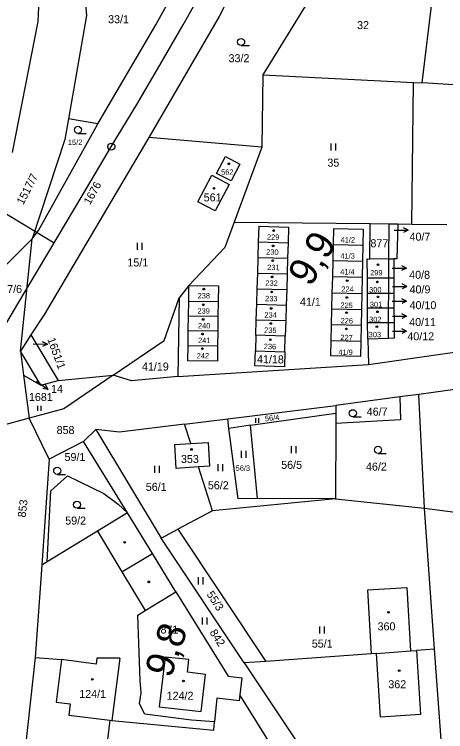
# Model space of a CAD drawing. Extents: x -553916 to -552953, y -1067469 to -1066637.
# Drawn here: x -553569.1 to -553477.6, y -1067307 to -1067154.7 of the extents above; entities that cross this region are included whole.
import ezdxf

# ---------------------------------------------------------------- set-up
doc = ezdxf.new("R2010")
doc.units = 0
for name, color, linetype in [('Hranice parcel', 7, 'Continuous'), ('Kolej', 7, 'Continuous'), ('Návěst místo trati', 7, 'Continuous'), ('Parcelní čísla', 7, 'Continuous'), ('Pop  PČ popisy', 7, 'Continuous'), ('Propustek', 7, 'Continuous'), ('Vnitřní kresba', 7, 'Continuous'), ('Vrstva 1', 7, 'Continuous'), ('Značky budov', 7, 'Continuous'), ('Značky kultur', 7, 'Continuous')]:
    doc.layers.add(name, color=color, linetype=linetype)

msp = doc.modelspace()

# ---------------------------------------------------------------- linework, layer by layer
at = {"layer": 'Hranice parcel'}
for p, q in [((-553499.73, -1067140.34), (-553516.39, -1067167.53)), ((-553499.73, -1067140.34), (-553516.39, -1067167.53)), ((-553482.63, -1067169.28), (-553479.18, -1067140.92)), ((-553516.39, -1067167.53), (-553516.62, -1067182.93)), ((-553516.39, -1067167.53), (-553516.62, -1067182.93)), ((-553516.39, -1067167.53), (-553484.43, -1067169.19)), ((-553484.83, -1067199.23), (-553484.43, -1067169.19)), ((-553484.43, -1067169.19), (-553482.63, -1067169.28)), ((-553551.38, -1067177.98), (-553557.64, -1067176.88)), ((-553516.62, -1067182.93), (-553540.6, -1067180.86)), ((-553516.62, -1067182.93), (-553522.52, -1067198.86)), ((-553516.62, -1067182.93), (-553522.52, -1067198.86)), ((-553522.52, -1067198.86), (-553493.67, -1067199.14)), ((-553493.69, -1067206.69), (-553493.67, -1067199.14)), ((-553493.67, -1067199.14), (-553489.7, -1067199.18)), ((-553489.7, -1067199.18), (-553489.74, -1067206.64)), ((-553489.7, -1067199.18), (-553487.77, -1067199.2)), ((-553487.77, -1067199.2), (-553484.83, -1067199.23)), ((-553484.83, -1067199.23), (-553477.39, -1067199.3)), ((-553517.41, -1067206.32), (-553517.31, -1067203.01)), ((-553517.31, -1067203.01), (-553511.06, -1067203.19)), ((-553511.06, -1067203.19), (-553511.16, -1067206.5)), ((-553501.52, -1067207), (-553501.44, -1067203.6)), ((-553501.44, -1067203.6), (-553495.2, -1067203.73)), ((-553495.2, -1067203.73), (-553495.27, -1067207.14)), ((-553517.5, -1067209.63), (-553517.41, -1067206.32)), ((-553517.41, -1067206.32), (-553511.16, -1067206.5)), ((-553511.16, -1067206.5), (-553511.26, -1067209.81)), ((-553501.59, -1067210.41), (-553501.52, -1067207)), ((-553501.52, -1067207), (-553495.27, -1067207.14)), ((-553495.27, -1067207.14), (-553495.34, -1067210.55)), ((-553489.74, -1067206.64), (-553493.69, -1067206.69)), ((-553489.74, -1067206.64), (-553489.76, -1067210.67)), ((-553489.74, -1067206.64), (-553488.62, -1067206.63)), ((-553488.62, -1067206.63), (-553488.61, -1067210.66)), ((-553517.6, -1067212.97), (-553517.5, -1067209.63)), ((-553517.5, -1067209.63), (-553511.26, -1067209.81)), ((-553511.26, -1067209.81), (-553511.35, -1067213.12)), ((-553501.67, -1067213.82), (-553501.59, -1067210.41)), ((-553495.34, -1067210.55), (-553501.59, -1067210.41)), ((-553495.34, -1067210.55), (-553495.42, -1067213.96)), ((-553494.21, -1067210.69), (-553489.76, -1067210.67)), ((-553494.2, -1067213.93), (-553494.21, -1067210.69)), ((-553489.76, -1067210.67), (-553489.78, -1067213.91)), ((-553489.76, -1067210.67), (-553488.61, -1067210.66)), ((-553488.61, -1067210.66), (-553488.6, -1067213.9)), ((-553532.09, -1067212.3), (-553534.18, -1067214.93)), ((-553532.09, -1067212.3), (-553534.18, -1067214.93)), ((-553517.7, -1067216.24), (-553517.6, -1067212.97)), ((-553517.6, -1067212.97), (-553511.35, -1067213.12)), ((-553511.35, -1067213.12), (-553511.45, -1067216.43)), ((-553534.18, -1067214.93), (-553534.41, -1067231.61)), ((-553501.74, -1067217.23), (-553501.67, -1067213.82)), ((-553501.67, -1067213.82), (-553495.42, -1067213.96)), ((-553495.42, -1067213.96), (-553495.49, -1067217.37)), ((-553494.2, -1067213.93), (-553489.78, -1067213.91)), ((-553494.18, -1067217.04), (-553494.2, -1067213.93)), ((-553489.78, -1067213.91), (-553489.8, -1067217.02)), ((-553489.78, -1067213.91), (-553488.6, -1067213.9)), ((-553488.6, -1067213.9), (-553488.59, -1067217.02)), ((-553532.18, -1067218.74), (-553532.14, -1067215.62)), ((-553532.14, -1067215.62), (-553525.89, -1067215.7)), ((-553525.89, -1067215.7), (-553525.93, -1067218.82)), ((-553517.8, -1067219.55), (-553517.7, -1067216.24)), ((-553517.7, -1067216.24), (-553511.45, -1067216.43)), ((-553511.45, -1067216.43), (-553511.55, -1067219.74)), ((-553501.82, -1067220.64), (-553501.74, -1067217.23)), ((-553501.74, -1067217.23), (-553495.49, -1067217.37)), ((-553495.49, -1067217.37), (-553495.57, -1067220.78)), ((-553494.18, -1067217.04), (-553489.8, -1067217.02)), ((-553494.17, -1067220.15), (-553494.18, -1067217.04)), ((-553489.8, -1067217.02), (-553489.82, -1067220.13)), ((-553489.8, -1067217.02), (-553488.59, -1067217.02)), ((-553488.59, -1067217.02), (-553488.57, -1067220.13)), ((-553532.22, -1067221.86), (-553532.18, -1067218.74)), ((-553532.18, -1067218.74), (-553525.93, -1067218.82)), ((-553525.93, -1067218.82), (-553525.97, -1067221.94)), ((-553517.89, -1067222.86), (-553517.8, -1067219.55)), ((-553517.8, -1067219.55), (-553511.55, -1067219.74)), ((-553511.55, -1067219.74), (-553511.65, -1067223.05)), ((-553501.89, -1067224.05), (-553501.82, -1067220.64)), ((-553495.57, -1067220.78), (-553501.82, -1067220.64)), ((-553495.57, -1067220.78), (-553495.64, -1067224.19)), ((-553494.17, -1067220.15), (-553489.82, -1067220.13)), ((-553494.11, -1067223.65), (-553494.17, -1067220.15)), ((-553489.82, -1067220.13), (-553489.84, -1067223.52)), ((-553489.82, -1067220.13), (-553488.57, -1067220.13)), ((-553532.26, -1067224.99), (-553532.22, -1067221.86)), ((-553532.22, -1067221.86), (-553525.97, -1067221.94)), ((-553525.97, -1067221.94), (-553526.01, -1067225.07)), ((-553517.89, -1067222.86), (-553517.99, -1067226.17)), ((-553511.65, -1067223.05), (-553517.89, -1067222.86)), ((-553511.74, -1067226.35), (-553511.65, -1067223.05)), ((-553495.64, -1067224.19), (-553501.89, -1067224.05)), ((-553489.84, -1067223.52), (-553494.11, -1067223.65)), ((-553494.11, -1067223.65), (-553494.01, -1067229.02)), ((-553532.26, -1067224.99), (-553526.01, -1067225.07)), ((-553517.99, -1067226.17), (-553511.74, -1067226.35)), ((-553534.41, -1067231.61), (-553494.01, -1067229.02)), ((-553559.8, -1067232.48), (-553548.15, -1067231.32)), ((-553548.15, -1067231.32), (-553558.62, -1067238.44)), ((-553548.15, -1067231.32), (-553558.62, -1067238.44)), ((-553487.37, -1067235.93), (-553500.94, -1067237.78)), ((-553483.33, -1067235.39), (-553487.37, -1067235.93)), ((-553482.12, -1067259.57), (-553483.33, -1067235.39)), ((-553523.81, -1067240.58), (-553500.94, -1067237.78)), ((-553500.94, -1067237.78), (-553500.94, -1067239.37)), ((-553558.62, -1067238.44), (-553566.01, -1067240.46)), ((-553558.62, -1067238.44), (-553566.01, -1067240.46)), ((-553566.01, -1067240.46), (-553574.19, -1067242.71)), ((-553561.75, -1067249.13), (-553566.01, -1067240.46)), ((-553533.05, -1067241.71), (-553523.81, -1067240.58)), ((-553523.62, -1067242.61), (-553523.81, -1067240.58)), ((-553519.03, -1067241.9), (-553500.94, -1067239.37)), ((-553500.94, -1067239.37), (-553500.95, -1067241.58)), ((-553531.71, -1067245.83), (-553533.05, -1067241.71)), ((-553519.03, -1067241.9), (-553523.62, -1067242.61)), ((-553517.54, -1067257.47), (-553519.03, -1067241.9)), ((-553500.95, -1067241.58), (-553501.02, -1067257.55)), ((-553551.83, -1067242.86), (-553554.44, -1067245.43)), ((-553551.83, -1067242.86), (-553538.01, -1067265.93)), ((-553554.44, -1067245.43), (-553561.75, -1067249.13)), ((-553545.12, -1067260.53), (-553554.44, -1067245.43)), ((-553535.1, -1067246.05), (-553531.71, -1067245.83)), ((-553534.78, -1067251.11), (-553535.1, -1067246.05)), ((-553531.71, -1067245.83), (-553528.01, -1067245.58)), ((-553528.01, -1067245.58), (-553527.7, -1067250.64)), ((-553561.75, -1067249.13), (-553563.32, -1067271.64)), ((-553530.08, -1067250.8), (-553534.78, -1067251.11)), ((-553527.7, -1067250.64), (-553530.08, -1067250.8)), ((-553527.05, -1067260.1), (-553530.08, -1067250.8)), ((-553562.14, -1067270.92), (-553561.36, -1067255.86)), ((-553501.02, -1067257.55), (-553527.05, -1067260.1)), ((-553501.02, -1067257.55), (-553517.54, -1067257.47)), ((-553501.02, -1067257.55), (-553482.12, -1067259.57)), ((-553545.12, -1067260.53), (-553551.5, -1067264.43)), ((-553527.05, -1067260.1), (-553534.46, -1067264.04)), ((-553482.12, -1067259.57), (-553452.56, -1067263.4)), ((-553479.96, -1067289.49), (-553482.12, -1067259.57)), ((-553551.5, -1067264.43), (-553562.14, -1067270.92)), ((-553538.01, -1067265.93), (-553534.46, -1067264.04)), ((-553534.46, -1067264.04), (-553515.77, -1067292.08)), ((-553520.36, -1067292.41), (-553538.01, -1067265.93)), ((-553562.14, -1067270.92), (-553563.32, -1067271.64)), ((-553563.32, -1067271.64), (-553564.68, -1067291.26)), ((-553479.96, -1067289.49), (-553483.79, -1067289.77)), ((-553477.8, -1067319.49), (-553479.96, -1067289.49)), ((-553493.35, -1067290.46), (-553515.77, -1067292.08)), ((-553492.3, -1067290.38), (-553493.35, -1067290.46)), ((-553492.3, -1067290.38), (-553485.06, -1067289.86)), ((-553485.06, -1067289.86), (-553483.79, -1067289.77)), ((-553564.68, -1067291.26), (-553568.7, -1067327.71)), ((-553515.77, -1067292.08), (-553520.36, -1067292.41)), ((-553510.29, -1067316.85), (-553521.28, -1067299.18)), ((-553526.79, -1067306.68), (-553526.63, -1067304.95))]:
    msp.add_line(p, q, dxfattribs=at)
for points in [[(-553556.09, -1067128.27), (-553553.82, -1067154.93), (-553557.64, -1067176.88)], [(-553569.54, -1067184.03), (-553564.06, -1067156.23), (-553562.87, -1067130.27)], [(-553436.84, -1067169.66), (-553454.76, -1067170.99), (-553482.63, -1067169.28)], [(-553557.64, -1067176.88), (-553558.41, -1067181.28), (-553565.31, -1067202.34)], [(-553523.15, -1067190.09), (-553526.22, -1067188.47), (-553524.32, -1067184.87), (-553521.26, -1067186.49), (-553523.15, -1067190.09)], [(-553527.24, -1067188.87), (-553523.54, -1067190.82), (-553526.51, -1067196.46), (-553530.21, -1067194.5), (-553527.24, -1067188.87)], [(-553522.52, -1067198.86), (-553524.5, -1067204.2), (-553532.09, -1067212.3)], [(-553522.52, -1067198.86), (-553524.5, -1067204.2), (-553532.09, -1067212.3)], [(-553517.31, -1067203.01), (-553517.21, -1067199.7), (-553510.96, -1067199.89), (-553511.06, -1067203.19)], [(-553487.77, -1067199.2), (-553487.95, -1067206.65), (-553488.62, -1067206.63)], [(-553501.44, -1067203.6), (-553501.37, -1067200.19), (-553495.12, -1067200.32), (-553495.2, -1067203.73)], [(-553494.21, -1067210.69), (-553494.24, -1067206.65), (-553493.69, -1067206.69)], [(-553532.14, -1067215.62), (-553532.09, -1067212.3), (-553525.84, -1067212.38), (-553525.89, -1067215.7)], [(-553548.15, -1067231.32), (-553537.32, -1067223.95), (-553534.18, -1067214.93)], [(-553548.15, -1067231.32), (-553537.32, -1067223.95), (-553534.18, -1067214.93)], [(-553488.57, -1067220.13), (-553488.56, -1067223.48), (-553489.84, -1067223.52)], [(-553495.64, -1067224.19), (-553495.71, -1067227.39), (-553501.96, -1067227.25), (-553501.89, -1067224.05)], [(-553526.01, -1067225.07), (-553526.05, -1067228.38), (-553532.3, -1067228.3), (-553532.26, -1067224.99)], [(-553494.01, -1067229.02), (-553464.41, -1067224.79), (-553459.11, -1067224.45)], [(-553511.74, -1067226.35), (-553511.84, -1067229.55), (-553518.08, -1067229.37), (-553517.99, -1067226.17)], [(-553534.41, -1067231.61), (-553544.27, -1067232.51), (-553548.15, -1067231.32)], [(-553452.74, -1067232.95), (-553465.5, -1067232.97), (-553483.33, -1067235.39)], [(-553487.37, -1067235.93), (-553487.19, -1067240.83), (-553500.95, -1067241.58)], [(-553533.05, -1067241.71), (-553546.78, -1067243.39), (-553551.83, -1067242.86)], [(-553517.54, -1067257.47), (-553521.67, -1067257.55), (-553523.62, -1067242.61)], [(-553561.36, -1067255.86), (-553557.88, -1067252.72), (-553550.14, -1067256.47), (-553547.08, -1067258.69), (-553545.12, -1067260.53)], [(-553534.89, -1067277.32), (-553539.83, -1067269.21), (-553545.12, -1067260.53)], [(-553542.96, -1067282.26), (-553541.37, -1067281.29), (-553534.89, -1067277.32)], [(-553534.89, -1067277.32), (-553523.75, -1067295.23), (-553520.84, -1067295.56), (-553521.28, -1067299.18)], [(-553493.35, -1067290.46), (-553494.13, -1067276.91), (-553485.86, -1067276.4), (-553485.06, -1067289.86)], [(-553526.63, -1067304.95), (-553531.57, -1067304.55), (-553541.46, -1067303.26), (-553542.6, -1067301.09), (-553542.21, -1067298.73), (-553542.41, -1067296.13), (-553542.96, -1067282.26)], [(-553483.79, -1067289.77), (-553482.94, -1067303.39), (-553491.45, -1067303.91), (-553492.3, -1067290.38)], [(-553564.68, -1067291.26), (-553559.12, -1067291.7), (-553560.24, -1067300.71), (-553557.31, -1067301.11), (-553557.58, -1067303.48), (-553548.89, -1067304.57)], [(-553538.38, -1067301.73), (-553529.52, -1067302.76), (-553528.59, -1067294.86), (-553532.42, -1067294.4), (-553532.11, -1067291.72), (-553537.15, -1067291.16), (-553538.38, -1067301.73)], [(-553520.36, -1067292.41), (-553507.33, -1067311.94), (-553506.4, -1067315.83), (-553505.07, -1067332.62)], [(-553521.28, -1067299.18), (-553521.44, -1067300.48), (-553526.17, -1067299.9), (-553526.63, -1067304.95)], [(-553548.89, -1067304.57), (-553550.06, -1067314.58), (-553541.86, -1067315.26), (-553538.68, -1067319.9), (-553539.08, -1067328.03)], [(-553548.89, -1067304.57), (-553548.47, -1067304.62), (-553526.79, -1067306.68)]]:
    msp.add_lwpolyline(points, dxfattribs=at)
at = {"layer": 'Kolej'}
for points in [[(-553543.17, -1067173.82), (-553538.26, -1067165.53), (-553533.28, -1067156.93), (-553528.57, -1067148.43), (-553524.02, -1067139.63), (-553519.75, -1067130.49), (-553515.84, -1067120.93), (-553512.27, -1067110.73), (-553509.46, -1067101.06), (-553507.13, -1067091.41), (-553505.08, -1067080.38), (-553504.39, -1067075.58), (-553503.32, -1067065.81)], [(-553559.81, -1067201.78), (-553554.74, -1067193.25), (-553548.48, -1067182.73), (-553543.17, -1067173.82)], [(-553578.03, -1067233.27), (-553575, -1067227.63), (-553571.43, -1067221.33), (-553568.36, -1067216.14), (-553564.22, -1067209.17), (-553559.81, -1067201.78)], [(-553578.03, -1067233.27), (-553575, -1067227.63), (-553571.43, -1067221.33), (-553568.36, -1067216.14), (-553564.22, -1067209.17), (-553559.81, -1067201.78)], [(-553578.03, -1067233.27), (-553575, -1067227.63), (-553571.43, -1067221.33), (-553568.36, -1067216.14), (-553564.22, -1067209.17), (-553559.81, -1067201.78)]]:
    msp.add_lwpolyline(points, dxfattribs=at)
at = {"layer": 'Návěst místo trati'}
msp.add_circle((-553548.52, -1067182.8), 0.75, dxfattribs=at)
at = {"layer": 'Pop  PČ popisy'}
for p, q in [((-553488.55, -1067200.5), (-553485.55, -1067200.55)), ((-553485.55, -1067200.55), (-553486.56, -1067201.04)), ((-553485.55, -1067200.55), (-553486.54, -1067200.03)), ((-553488.95, -1067208.58), (-553485.95, -1067208.63)), ((-553485.95, -1067208.63), (-553486.96, -1067209.12)), ((-553485.95, -1067208.63), (-553486.94, -1067208.11)), ((-553488.88, -1067212.46), (-553485.88, -1067212.46)), ((-553485.88, -1067212.46), (-553486.88, -1067211.96)), ((-553485.88, -1067212.46), (-553486.88, -1067212.96)), ((-553488.94, -1067215.58), (-553485.94, -1067215.58)), ((-553485.94, -1067215.58), (-553486.94, -1067215.08)), ((-553485.94, -1067215.58), (-553486.94, -1067216.08)), ((-553488.91, -1067218.79), (-553485.91, -1067218.79)), ((-553485.91, -1067218.79), (-553486.91, -1067218.29)), ((-553485.91, -1067218.79), (-553486.91, -1067219.29)), ((-553488.93, -1067222.01), (-553485.93, -1067221.96)), ((-553485.93, -1067221.96), (-553486.94, -1067221.47)), ((-553485.93, -1067221.96), (-553486.92, -1067222.48)), ((-553565.13, -1067224.69), (-553562.12, -1067224.75)), ((-553562.12, -1067224.75), (-553563.14, -1067225.23)), ((-553562.12, -1067224.75), (-553563.12, -1067224.23)), ((-553564.42, -1067232.61), (-553561.97, -1067234.35)), ((-553561.97, -1067234.35), (-553563.08, -1067234.18)), ((-553561.97, -1067234.35), (-553562.5, -1067233.36))]:
    msp.add_line(p, q, dxfattribs=at)
at = {"layer": 'Propustek'}
msp.add_lwpolyline([(-553609.73, -1067167.48), (-553572.5, -1067189.62), (-553572.38, -1067196.18), (-553560.65, -1067203.19)], dxfattribs=at)
at = {"layer": 'Vnitřní kresba'}
for p, q in [((-553551.5, -1067264.43), (-553546.3, -1067273.09)), ((-553546.3, -1067273.09), (-553539.83, -1067269.21)), ((-553546.3, -1067273.09), (-553541.37, -1067281.29)), ((-553551.76, -1067292.67), (-553559.12, -1067291.7)), ((-553551.61, -1067291.4), (-553551.76, -1067292.67)), ((-553546.75, -1067291.4), (-553551.61, -1067291.4)), ((-553546.75, -1067291.4), (-553548.47, -1067304.62))]:
    msp.add_line(p, q, dxfattribs=at)
at = {"layer": 'Vrstva 1'}
for p, q in [((-553565.31, -1067202.34), (-553574.87, -1067211.83)), ((-553567.81, -1067226.24), (-553565.31, -1067202.34)), ((-553565.59, -1067222.79), (-553567.81, -1067226.24)), ((-553565.59, -1067222.79), (-553567.81, -1067226.24)), ((-553565.59, -1067222.79), (-553559.8, -1067232.48)), ((-553563.49, -1067233.47), (-553567.81, -1067226.24)), ((-553567.81, -1067226.24), (-553567.17, -1067231.29)), ((-553567.17, -1067231.29), (-553563.49, -1067233.47)), ((-553567.17, -1067231.29), (-553566.01, -1067240.46)), ((-553563.49, -1067233.47), (-553559.8, -1067232.48)), ((-553566.01, -1067240.46), (-553574.19, -1067242.71))]:
    msp.add_line(p, q, dxfattribs=at)
for points in [[(-553551.38, -1067177.98), (-553539.14, -1067156.92), (-553532.35, -1067144.53)], [(-553520.16, -1067144.23), (-553525.7, -1067155.19), (-553540.6, -1067180.86)], [(-553565.31, -1067202.34), (-553564.03, -1067200.6), (-553552.18, -1067179.37), (-553551.38, -1067177.98)], [(-553540.6, -1067180.86), (-553562.72, -1067218.38), (-553565.59, -1067222.79)]]:
    msp.add_lwpolyline(points, dxfattribs=at)
at = {"layer": 'Značky budov'}
for centre in [(-553523.62, -1067186.44), (-553526.78, -1067191.65), (-553514.12, -1067200.61), (-553514.22, -1067203.87), (-553514.32, -1067207.02), (-553491.97, -1067207.89), (-553514.42, -1067210.46), (-553498.5, -1067211.24), (-553492.1, -1067211.52), (-553528.94, -1067213.05), (-553514.54, -1067213.64), (-553498.57, -1067214.83), (-553491.97, -1067214.7), (-553529.04, -1067216.38), (-553514.63, -1067217.15), (-553498.64, -1067218.04), (-553492.08, -1067217.87), (-553529.07, -1067219.49), (-553514.72, -1067220.35), (-553492.22, -1067221.02), (-553529.21, -1067222.61), (-553498.71, -1067221.49), (-553514.82, -1067223.79), (-553529.23, -1067225.7), (-553531.54, -1067247.09), (-553545.71, -1067266.8), (-553540.6, -1067275.21), (-553489.76, -1067281.68), (-553487.47, -1067294.05), (-553552.59, -1067295.91), (-553533.24, -1067296.25)]:
    msp.add_circle(centre, 0.175, dxfattribs=at)
at = {"layer": 'Značky kultur'}
for p, q in [((-553521.02, -1067161.33), (-553519.27, -1067161.33)), ((-553555.63, -1067179.99), (-553553.88, -1067179.99)), ((-553501.91, -1067183.64), (-553501.91, -1067182.14)), ((-553500.91, -1067183.64), (-553500.91, -1067182.14)), ((-553543, -1067204.69), (-553543, -1067203.19)), ((-553542, -1067204.69), (-553542, -1067203.19)), ((-553564.13, -1067238.86), (-553564.13, -1067237.86)), ((-553563.46, -1067238.86), (-553563.46, -1067237.86)), ((-553517.92, -1067241.44), (-553517.92, -1067240.44)), ((-553517.25, -1067241.44), (-553517.25, -1067240.44)), ((-553497.32, -1067240.15), (-553495.57, -1067240.15)), ((-553510.36, -1067247.88), (-553510.36, -1067246.38)), ((-553509.36, -1067247.88), (-553509.36, -1067246.38)), ((-553520.92, -1067248.89), (-553520.92, -1067247.39)), ((-553519.92, -1067248.89), (-553519.92, -1067247.39)), ((-553491.97, -1067247.92), (-553490.22, -1067247.92)), ((-553539.35, -1067252.05), (-553539.35, -1067250.55)), ((-553538.35, -1067252.05), (-553538.35, -1067250.55)), ((-553525.89, -1067251.71), (-553525.89, -1067250.21)), ((-553524.89, -1067251.71), (-553524.89, -1067250.21)), ((-553560.03, -1067252.38), (-553558.28, -1067252.38)), ((-553555.83, -1067259.57), (-553554.08, -1067259.57)), ((-553530.06, -1067275.73), (-553530.06, -1067274.23)), ((-553529.06, -1067275.73), (-553529.06, -1067274.23)), ((-553529.23, -1067284.28), (-553529.23, -1067282.78)), ((-553528.23, -1067284.28), (-553528.23, -1067282.78)), ((-553504.34, -1067286.18), (-553504.34, -1067284.68)), ((-553503.34, -1067286.18), (-553503.34, -1067284.68))]:
    msp.add_line(p, q, dxfattribs=at)
for centre in [(-553521.02, -1067160.58), (-553555.63, -1067179.24), (-553497.32, -1067239.4), (-553491.97, -1067247.17), (-553560.02, -1067251.63), (-553555.83, -1067258.82)]:
    msp.add_circle(centre, 0.75, dxfattribs=at)

# ---------------------------------------------------------------- texts
at = {"layer": 'Návěst místo trati'}
for s, rotation, p in [('9,9', 59.2372, (-553506.29, -1067212.77)), ('9,8', 70.9465, (-553535.94, -1067295.85))]:
    msp.add_text(s, height=6, rotation=rotation, dxfattribs=at).set_placement(p)
at = {"layer": 'Parcelní čísla'}
for s, height, p in [('33/1', 1.7, (-553549.23, -1067156.6)), ('32', 1.7, (-553496.42, -1067157.85)), ('33/2', 1.7, (-553523.68, -1067164.88)), ('15/2', 1.14, (-553557.77, -1067182.45)), ('35', 1.7, (-553502.71, -1067187.05)), ('562', 1.14, (-553525.25, -1067188.77)), ('561', 1.7, (-553528.95, -1067194.43)), ('40/7', 1.7, (-553485.29, -1067202.76)), ('41/2', 1.14, (-553499.91, -1067203.16)), ('877', 1.7, (-553493.58, -1067204.16)), ('41/3', 1.14, (-553499.95, -1067206.59)), ('15/1', 1.7, (-553545.14, -1067208.24)), ('41/4', 1.14, (-553499.98, -1067209.95)), ('299', 1.14, (-553493.64, -1067210.14)), ('40/8', 1.7, (-553485.36, -1067210.86)), ('224', 1.14, (-553499.75, -1067213.62)), ('300', 1.14, (-553493.86, -1067213.75)), ('40/9', 1.7, (-553485.28, -1067213.96)), ('238', 1.14, (-553530.24, -1067215.02)), ('41/1', 1.7, (-553508.54, -1067216.59)), ('301', 1.14, (-553493.7, -1067216.89)), ('40/10', 1.7, (-553485.28, -1067217.31)), ('239', 1.14, (-553530.27, -1067218.25)), ('234', 1.14, (-553516.07, -1067219.1)), ('302', 1.14, (-553493.87, -1067220.07)), ('40/11', 1.7, (-553485.37, -1067220.89)), ('240', 1.14, (-553530.17, -1067221.4)), ('303', 1.14, (-553493.95, -1067223.27)), ('40/12', 1.7, (-553485.75, -1067223.92)), ('241', 1.14, (-553530.14, -1067224.51)), ('242', 1.14, (-553530.43, -1067227.77)), ('41/9', 1.14, (-553500.39, -1067227.03)), ('41/19', 1.7, (-553542.05, -1067230.33)), ('1681', 1.7, (-553566.03, -1067236.81)), ('46/7', 1.7, (-553494.37, -1067239.91)), ('858', 1.7, (-553560.16, -1067243.82)), ('59/1', 1.7, (-553558.48, -1067249.55)), ('353', 1.7, (-553533.77, -1067249.97)), ('56/5', 1.7, (-553512.51, -1067251.21)), ('46/2', 1.7, (-553494.53, -1067251.58)), ('56/3', 1.14, (-553522.18, -1067251.63)), ('56/1', 1.7, (-553541.24, -1067255.88)), ('56/2', 1.7, (-553528.07, -1067255.54)), ('59/2', 1.7, (-553558.33, -1067263.04)), ('871', 1.7, (-553538.11, -1067286.17)), ('360', 1.7, (-553492.07, -1067285.5)), ('55/1', 1.7, (-553506.02, -1067289.16)), ('362', 1.7, (-553489.79, -1067297.79)), ('124/1', 1.7, (-553555.35, -1067299.85)), ('124/2', 1.7, (-553536.81, -1067300.23))]:
    msp.add_text(s, height=height, dxfattribs=at).set_placement(p)
for s, height, rotation, p in [('1517/7', 1.7, 63, (-553567.22, -1067195.27)), ('229', 1.14, 359, (-553515.54, -1067202.54)), ('230', 1.14, 358, (-553515.72, -1067205.7)), ('231', 1.14, 359, (-553515.48, -1067208.99)), ('232', 1.14, 359, (-553515.87, -1067212.33)), ('233', 1.14, 359, (-553515.93, -1067215.61)), ('225', 1.14, 358, (-553499.96, -1067217)), ('226', 1.14, 359, (-553499.92, -1067220.31)), ('235', 1.14, 358, (-553516.15, -1067222.3)), ('227', 1.14, 358, (-553499.97, -1067223.85)), ('236', 1.14, 359, (-553516.22, -1067225.78)), ('41/18', 1.7, 359, (-553517.66, -1067228.74)), ('56/4', 1.14, 6, (-553515.91, -1067241.12)), ('853', 1.7, 83, (-553566.74, -1067261.61)), ('55/3', 1.7, 303, (-553528.42, -1067277.83)), ('842', 1.7, 303, (-553527.77, -1067285.94))]:
    msp.add_text(s, height=height, rotation=rotation, dxfattribs=at).set_placement(p)
at = {"layer": 'Vrstva 1'}
for s, rotation, p in [('1676', 61, (-553553.05, -1067195.26)), ('1651/1', 290, (-553562.15, -1067223.7))]:
    msp.add_text(s, height=1.7, rotation=rotation, dxfattribs=at).set_placement(p)
for s, p in [('1517/6', (-553574.44, -1067213.88)), ('14', (-553561.34, -1067235.08))]:
    msp.add_text(s, height=1.7, dxfattribs=at).set_placement(p)

doc.saveas('drawing.dxf')
